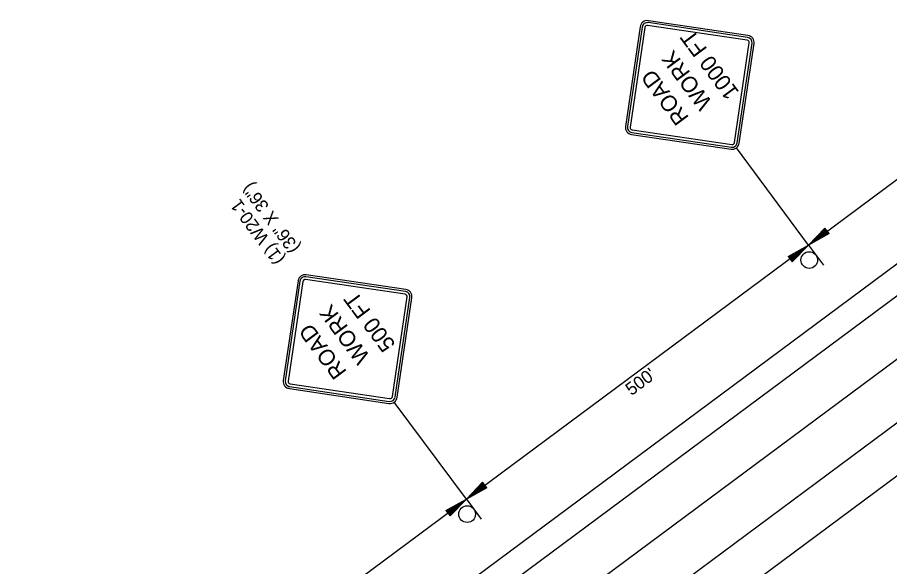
# Model space of a CAD drawing. Extents: x 998982 to 1000626, y 1875366 to 1876934.
# Drawn here: x 999829.6 to 1000238.9, y 1876250.2 to 1876507.9 of the extents above; entities that cross this region are included whole.
import ezdxf

# ---------------------------------------------------------------- set-up
doc = ezdxf.new("R2010")
doc.units = 0
for name, color, linetype in [('P_TC_Signs_Temporary', 7, 'Continuous'), ('R_Border Prem', 7, 'Continuous'), ('R_Draft', 7, 'Continuous'), ('STAMP', 7, 'Continuous')]:
    doc.layers.add(name, color=color, linetype=linetype)

msp = doc.modelspace()

# ---------------------------------------------------------------- linework, layer by layer
at = {"layer": 'P_TC_Signs_Temporary'}
for p, q in [((1000121.88, 1876503.49), (1000114.97, 1876456.75)), ((1000122.8, 1876503.35), (1000115.9, 1876456.61)), ((1000172.12, 1876497.2), (1000125.38, 1876504.11)), ((1000172.31, 1876498.5), (1000125.57, 1876505.41)), ((1000172.45, 1876499.43), (1000125.71, 1876506.33)), ((1000124.1, 1876503.16), (1000117.2, 1876456.42)), ((1000166.16, 1876449.18), (1000173.07, 1876495.92)), ((1000167.46, 1876448.99), (1000174.37, 1876495.73)), ((1000168.39, 1876448.85), (1000175.3, 1876495.6)), ((1000118.14, 1876455.14), (1000164.89, 1876448.23)), ((1000117.82, 1876452.91), (1000164.56, 1876446.01)), ((1000117.95, 1876453.84), (1000164.69, 1876446.93)), ((1000011.55, 1876377.97), (999964.81, 1876384.88)), ((1000011.74, 1876379.27), (999965, 1876386.17)), ((1000011.88, 1876380.2), (999965.13, 1876387.1)), ((999961.3, 1876384.26), (999954.4, 1876337.51)), ((999962.23, 1876384.12), (999955.32, 1876337.38)), ((999963.53, 1876383.93), (999956.62, 1876337.18)), ((1000005.59, 1876329.95), (1000012.5, 1876376.69)), ((1000006.89, 1876329.76), (1000013.8, 1876376.5)), ((1000007.82, 1876329.62), (1000014.72, 1876376.36)), ((999957.57, 1876335.91), (1000004.31, 1876329)), ((999957.24, 1876333.68), (1000003.98, 1876326.78)), ((999957.38, 1876334.61), (1000004.12, 1876327.7))]:
    msp.add_line(p, q, dxfattribs=at)
for centre, radius, start, end in [((1000125.21, 1876502.99), 3.38, 81.5953, 171.5953), ((1000125.21, 1876502.99), 2.44, 81.5953, 171.5953), ((1000125.21, 1876502.99), 1.12, 81.5953, 171.5953), ((1000171.96, 1876496.09), 3.38, 351.5953, 81.5953), ((1000171.96, 1876496.09), 1.13, 351.5953, 81.5953), ((1000171.96, 1876496.09), 2.44, 351.5953, 81.5953), ((1000118.31, 1876456.25), 3.38, 171.5953, 261.5953), ((1000118.31, 1876456.25), 2.44, 171.5953, 261.5953), ((1000118.31, 1876456.25), 1.13, 171.5953, 261.5953), ((1000165.05, 1876449.35), 3.38, 261.5953, 351.5953), ((1000165.05, 1876449.35), 2.44, 261.5953, 351.5953), ((1000165.05, 1876449.35), 1.12, 261.5953, 351.5953), ((999964.64, 1876383.76), 3.38, 81.5953, 171.5953), ((999964.64, 1876383.76), 2.44, 81.5953, 171.5953), ((999964.64, 1876383.76), 1.12, 81.5953, 171.5953), ((1000011.38, 1876376.86), 1.13, 351.5953, 81.5953), ((1000011.38, 1876376.86), 2.44, 351.5953, 81.5953), ((1000011.38, 1876376.86), 3.38, 351.5953, 81.5953), ((999957.74, 1876337.02), 3.38, 171.5953, 261.5953), ((999957.74, 1876337.02), 2.44, 171.5953, 261.5953), ((999957.74, 1876337.02), 1.13, 171.5953, 261.5953), ((1000004.48, 1876330.11), 3.38, 261.5953, 351.5953), ((1000004.48, 1876330.11), 2.44, 261.5953, 351.5953), ((1000004.48, 1876330.11), 1.12, 261.5953, 351.5953)]:
    msp.add_arc(centre, radius, start, end, dxfattribs=at)
at = {"layer": 'R_Draft'}
for p, q in [((1000200.89, 1876401.08), (1000361.46, 1876520.31)), ((1000380.5, 1876494.68), (999829.63, 1876085.64)), ((1000387.64, 1876485.07), (999836.77, 1876076.03)), ((1000401.91, 1876465.85), (999851.04, 1876056.81)), ((1000416.18, 1876446.63), (999865.31, 1876037.59)), ((1000200.89, 1876401.08), (1000167.06, 1876446.64)), ((1000428.07, 1876430.61), (999877.2, 1876021.57)), ((1000208.53, 1876409), (1000200.89, 1876401.08)), ((1000210.51, 1876406.41), (1000200.89, 1876401.08)), ((1000208.69, 1876408.79), (1000202.33, 1876402.19)), ((1000210.35, 1876406.63), (1000202.33, 1876402.19)), ((1000208.86, 1876408.57), (1000203.81, 1876403.33)), ((1000210.18, 1876406.85), (1000203.81, 1876403.33)), ((1000209.03, 1876408.35), (1000205.25, 1876404.43)), ((1000210.01, 1876407.06), (1000205.25, 1876404.43)), ((1000209.2, 1876408.13), (1000206.72, 1876405.55)), ((1000209.84, 1876407.29), (1000206.72, 1876405.55)), ((1000209.37, 1876407.91), (1000208.15, 1876406.66)), ((1000209.67, 1876407.5), (1000208.15, 1876406.66)), ((1000210.51, 1876406.41), (1000208.53, 1876409)), ((1000200.89, 1876401.08), (1000040.32, 1876281.85)), ((1000191.27, 1876395.75), (1000200.89, 1876401.08)), ((1000193.25, 1876393.16), (1000200.89, 1876401.08)), ((1000191.43, 1876395.54), (1000199.45, 1876399.97)), ((1000191.6, 1876395.31), (1000197.97, 1876398.84)), ((1000191.77, 1876395.1), (1000196.53, 1876397.73)), ((1000192.75, 1876393.81), (1000196.53, 1876397.73)), ((1000192.92, 1876393.6), (1000197.97, 1876398.84)), ((1000193.09, 1876393.38), (1000199.45, 1876399.97)), ((1000191.27, 1876395.75), (1000193.25, 1876393.16)), ((1000191.94, 1876394.88), (1000195.06, 1876396.61)), ((1000192.1, 1876394.66), (1000193.62, 1876395.5)), ((1000192.41, 1876394.25), (1000193.62, 1876395.5)), ((1000192.58, 1876394.03), (1000195.06, 1876396.61)), ((1000040.32, 1876281.85), (1000006.49, 1876327.4)), ((1000047.95, 1876289.77), (1000040.32, 1876281.85)), ((1000049.94, 1876287.18), (1000040.32, 1876281.85)), ((1000048.12, 1876289.55), (1000041.76, 1876282.96)), ((1000049.78, 1876287.39), (1000041.76, 1876282.96)), ((1000048.29, 1876289.33), (1000043.24, 1876284.09)), ((1000049.6, 1876287.62), (1000043.24, 1876284.09)), ((1000048.45, 1876289.12), (1000044.68, 1876285.2)), ((1000049.44, 1876287.83), (1000044.68, 1876285.2)), ((1000048.62, 1876288.9), (1000046.14, 1876286.32)), ((1000049.27, 1876288.05), (1000046.14, 1876286.32)), ((1000048.79, 1876288.68), (1000047.58, 1876287.43)), ((1000049.1, 1876288.27), (1000047.58, 1876287.43)), ((1000049.94, 1876287.18), (1000047.95, 1876289.77)), ((999879.74, 1876162.62), (1000040.32, 1876281.85)), ((1000030.69, 1876276.52), (1000040.32, 1876281.85)), ((1000030.86, 1876276.31), (1000038.88, 1876280.74)), ((1000031.03, 1876276.08), (1000037.39, 1876279.6)), ((1000031.19, 1876275.87), (1000035.95, 1876278.5)), ((1000032.18, 1876274.58), (1000035.95, 1876278.5)), ((1000032.34, 1876274.36), (1000037.39, 1876279.6)), ((1000032.51, 1876274.15), (1000038.88, 1876280.74)), ((1000032.68, 1876273.93), (1000040.32, 1876281.85)), ((1000030.69, 1876276.52), (1000032.68, 1876273.93)), ((1000031.37, 1876275.64), (1000034.49, 1876277.38)), ((1000031.53, 1876275.43), (1000033.05, 1876276.27)), ((1000031.84, 1876275.02), (1000033.05, 1876276.27)), ((1000032.01, 1876274.8), (1000034.49, 1876277.38))]:
    msp.add_line(p, q, dxfattribs=at)
at = {"layer": 'STAMP'}
for p, q in [((1000200.89, 1876401.08), (1000207.89, 1876391.64)), ((1000040.32, 1876281.85), (1000047.32, 1876272.41))]:
    msp.add_line(p, q, dxfattribs=at)
for centre in [(1000201.24, 1876394.03), (1000040.67, 1876274.8)]:
    msp.add_circle(centre, 3.92, dxfattribs=at)

# ---------------------------------------------------------------- texts
at = {"layer": 'P_TC_Signs_Temporary'}
for s, p in [('1000 FT', (1000168.58, 1876472.83)), ('WORK', (1000155.98, 1876467.95)), (' ROAD ', (1000146.69, 1876458.62)), ('500 FT ', (1000007.36, 1876354.46)), ('WORK', (999995.41, 1876348.71)), (' ROAD ', (999986.12, 1876339.39))]:
    msp.add_text(s, height=7.5, rotation=126.5953, dxfattribs=at).set_placement(p)
at = {"layer": 'R_Border Prem'}
for s, rotation, p in [('(36" X 36")', 126.5953, (999962.44, 1876399.91)), ('(1) W20-1', 126.5953, (999955.22, 1876394.54)), ("500'", 36.5953, (1000117.78, 1876330.13))]:
    msp.add_text(s, height=6, rotation=rotation, dxfattribs=at).set_placement(p)

doc.saveas('drawing.dxf')
